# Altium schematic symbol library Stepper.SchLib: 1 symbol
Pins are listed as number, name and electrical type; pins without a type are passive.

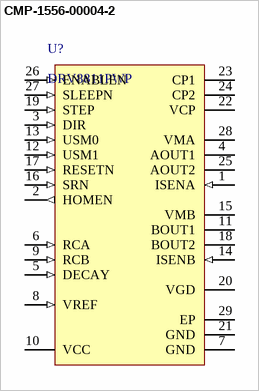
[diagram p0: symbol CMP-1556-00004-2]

## CMP-1556-00004-2
designator U?, comment DRV8811PWP
1.9 A Bipolar Stepper Motor Driver with On-Chip 1 / 8 Microstepping Indexer (Step / Dir Ctrl), -40 to 85 degC, 28-pin HTSSOP (PWP), Green (RoHS & no Sb/Br); Thermal Shutdown: TRUE; Peak Output Current(A): 1.9
footprint PWP0028C_M (SOP, 28-Leads, Body 9.8x4.5mm, Pitch 0.65mm, Thermal Pad 5.18x3.1mm, IPC Low Density)
footprint PWP0028C_L (SOP, 28-Leads, Body 9.8x4.5mm, Pitch 0.65mm, Thermal Pad 5.18x3.1mm, IPC High Density)
footprint PWP0028C_N (SOP, 28-Leads, Body 9.8x4.5mm, Pitch 0.65mm, Thermal Pad 5.18x3.1mm, IPC Medium Density)
pins: 1 ISENA (in) "Bridge A ground / Isense", 2 HOMEN (out) "Home position", 3 DIR (in) "Direction input", 4 AOUT1 (power) "Bridge A output 1", 5 DECAY (in) "Decay mode select", 6 RCA (in) "Bridge A blanking and off time adjust", 7 GND (power) "Device ground", 8 VREF (in) "Current set reference input", 9 RCB (in) "Bridge B blanking and off time adjust", 10 VCC (power) "Logic supply voltage", 11 BOUT1 (power) "Bridge B output 1", 12 USM1 (in) "Microstep mode 1", 13 USM0 (in) "Microstep mode 0", 14 ISENB (in) "Bridge B ground / Isense", 15 VMB (power) "Bridge B power supply", 16 SRN (in) "Sync. Rect. enable input", 17 RESETN (in) "Reset input", 18 BOUT2 (power) "Bridge B output 2", 19 STEP (in) "Step input", 20 VGD (power) "Low-side gate drive voltage", 21 GND (power) "Device ground", 22 VCP (power) "High-side gate drive voltage", 23 CP1 "Charge pump flying capacitor", 24 CP2 "Charge pump flying capacitor", 25 AOUT2 (power) "Bridge A output 2", 26 ENABLEN (in) "Enable input", 27 SLEEPN (in) "Sleep mode input", 28 VMA (power) "Bridge A power supply", 29 EP (power) "Exposed Thermal Pad"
